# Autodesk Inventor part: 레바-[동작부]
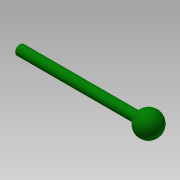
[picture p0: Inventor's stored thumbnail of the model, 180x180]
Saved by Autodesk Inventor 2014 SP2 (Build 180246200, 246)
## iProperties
Created: 2015-12
Part Number: 레바-[동작부]
Material: 스테인리스강
Document SubType Name: Modeling
Designer: mduedu
Density: 8.08 g/cm^3
Mass: 30.7693 g
Surface Area: 20.8622 cm^2
Volume: 3.80808 cm^3
Appearance: 진녹색
Author: mduedu
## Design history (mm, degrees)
sketch "스케치1"
  geometry: C1 r 3 at (0, 0); 1 further point
  constraints: 1 centre point, 1 coincident
  dimensions: "d0" = 6 diameter of C1
extrude "돌출1" new body sketch "스케치1" distance "d1" = 80; taper "d2" = 0 deg
sketch "스케치2"
  geometry: L1 (7.5, 0)-(-6, 0); L2 (-6, 4.5)-(-6, 0); A1 r 7.5 centre (0, 0) between (7.5, 0) and (-6, 4.5); 2 further points
  constraints: 4 end point, 2 coincident, 2 point on circle, 1 centre point, 1 horizontal, 1 perpendicular, 1 point on line
  dimensions: "d3" = 15 diameter of A1; "d10" = 6 distance from line of L2 point (0, 0)
revolve "회전1" sketch "스케치2" stored, may be unused: angle "d4" = 90 deg
chamfer "모따기1" distance "d7" = 0.5; stored, may be unused: second distance "d8" = 2, angle "d9" = 45 deg
fillet "모깎기2" dims "d11" = 0.3
node "솔리드1"
